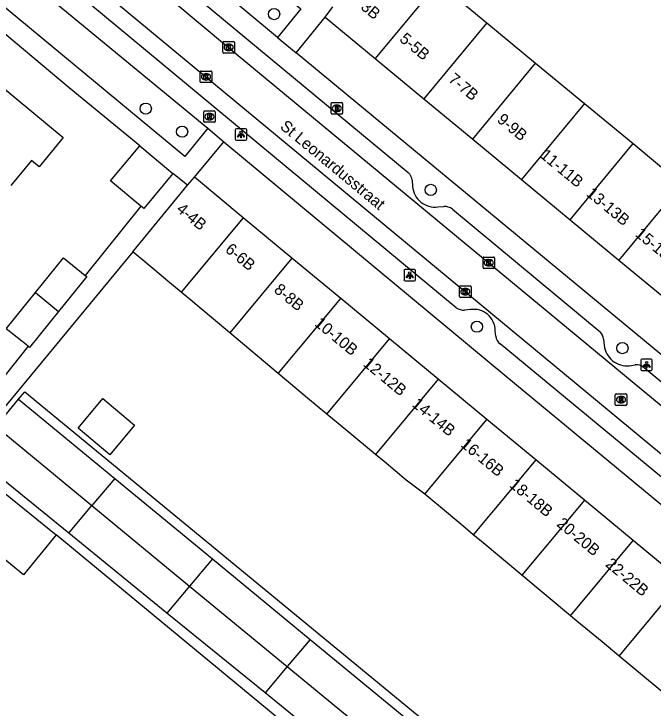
# Model space of a CAD drawing. Extents: x 162074 to 163034, y 381824 to 382557.
# Drawn here: x 162449 to 162504.7, y 382186.3 to 382246.8 of the extents above; entities that cross this region are included whole.
import ezdxf

# ---------------------------------------------------------------- set-up
doc = ezdxf.new("R2010")
doc.units = 0
for name, color, linetype in [('IMGEO_Boom', 7, 'Continuous'), ('IMGEO_Brandkraan', 7, 'Continuous'), ('IMGEO_Kolk', 7, 'Continuous'), ('IMGEO_Lichtpunt', 7, 'Continuous'), ('IMGEO_Muur', 7, 'Continuous'), ('IMGEO_Openbare_ruimte_label', 7, 'Continuous'), ('IMGEO_Pand', 7, 'Continuous'), ('IMGEO_Pand_nummerreeks', 7, 'Continuous'), ('IMGEO_Rijbaan_lokaal_open', 7, 'Continuous'), ('IMGEO_Rioolput', 7, 'Continuous'), ('IMGEO_Voetpad_open', 7, 'Continuous')]:
    doc.layers.add(name, color=color, linetype=linetype)

msp = doc.modelspace()

# ---------------------------------------------------------------- linework, layer by layer
at = {"layer": 'IMGEO_Boom'}
for centre in [(162471.704, 382246.766), (162460.522, 382238.531), (162463.692, 382236.523), (162485.349, 382231.451), (162489.366, 382219.536), (162502.038, 382217.668)]:
    msp.add_circle(centre, 0.489, dxfattribs=at)
at = {"layer": 'IMGEO_Brandkraan'}
for p, q in [((162476.665, 382238.132), (162476.665, 382238.984)), ((162476.74, 382239.058), (162477.592, 382239.058)), ((162477.153, 382238.838), (162477.178, 382238.838)), ((162477.666, 382238.984), (162477.666, 382238.132)), ((162477.176, 382238.278), (162477.151, 382238.278)), ((162477.592, 382238.058), (162476.74, 382238.058))]:
    msp.add_line(p, q, dxfattribs=at)
for points in [[(162476.665, 382238.132), (162476.665, 382238.984)], [(162476.74, 382239.058), (162477.592, 382239.058)], [(162477.013, 382238.758), (162477.013, 382238.358), (162477.226, 382238.358)], [(162477.244, 382238.758), (162477.013, 382238.758)], [(162477.666, 382238.984), (162477.666, 382238.132)], [(162477.192, 382238.677), (162477.138, 382238.677), (162477.138, 382238.601)], [(162477.138, 382238.601), (162477.191, 382238.601)], [(162477.2, 382238.525), (162477.138, 382238.525), (162477.138, 382238.444)], [(162477.138, 382238.444), (162477.2, 382238.444)], [(162477.592, 382238.058), (162476.74, 382238.058)]]:
    msp.add_lwpolyline(points, dxfattribs=at)
for centre, radius, start, end in [((162476.742, 382238.982), 0.0765, 91.55205, 178.44795), ((162476.742, 382238.982), 0.0765, 91.55205, 178.44795), ((162477.248, 382238.613), 0.145, 59.4692, 91.53667), ((162477.273, 382238.66), 0.0922, 285.51372, 58.15012), ((162477.59, 382238.982), 0.0765, 1.55205, 88.44795), ((162477.59, 382238.982), 0.0765, 1.55205, 88.44795), ((162476.742, 382238.134), 0.0765, 181.55205, 268.44795), ((162476.742, 382238.134), 0.0765, 181.55205, 268.44795), ((162477.193, 382238.639), 0.0379, 267.82845, 90.93552), ((162477.201, 382238.484), 0.0404, 269.87594, 90.50774), ((162477.232, 382238.609), 0.251, 268.66757, 293.53466), ((162477.278, 382238.468), 0.105, 301.31148, 78.98903), ((162477.59, 382238.134), 0.0765, 271.55205, 358.44795), ((162477.59, 382238.134), 0.0765, 271.55205, 358.44795)]:
    msp.add_arc(centre, radius, start, end, dxfattribs=at)
for centre, major_axis, ratio, start_param, end_param in [((162477.152, 382238.558), (-0.387, 0.002), 0.722429, 4.712389, 7.853982), ((162477.177, 382238.558), (-0.39, 0.002), 0.717154, 1.570796, 4.712389)]:
    msp.add_ellipse(centre, major_axis=major_axis, ratio=ratio, start_param=start_param, end_param=end_param, dxfattribs=at)
at = {"layer": 'IMGEO_Kolk'}
for p, q in [((162467.242, 382243.437), (162467.242, 382244.289)), ((162467.317, 382244.363), (162468.169, 382244.363)), ((162468.243, 382244.289), (162468.243, 382243.437)), ((162467.753, 382243.583), (162467.728, 382243.583)), ((162467.73, 382244.143), (162467.755, 382244.143)), ((162468.169, 382243.363), (162467.317, 382243.363)), ((162465.273, 382240.876), (162465.273, 382241.728)), ((162465.348, 382241.802), (162466.2, 382241.802)), ((162466.274, 382241.728), (162466.274, 382240.876)), ((162465.761, 382241.582), (162465.786, 382241.582)), ((162466.2, 382240.802), (162465.348, 382240.802)), ((162465.784, 382241.022), (162465.759, 382241.022)), ((162489.896, 382224.679), (162489.896, 382225.531)), ((162489.971, 382225.605), (162490.823, 382225.605)), ((162490.897, 382225.531), (162490.897, 382224.679)), ((162490.407, 382224.825), (162490.382, 382224.825)), ((162490.384, 382225.385), (162490.409, 382225.385)), ((162490.823, 382224.605), (162489.971, 382224.605)), ((162487.856, 382222.165), (162487.856, 382223.017)), ((162487.931, 382223.091), (162488.783, 382223.091)), ((162488.857, 382223.017), (162488.857, 382222.165)), ((162488.344, 382222.871), (162488.369, 382222.871)), ((162488.783, 382222.091), (162487.931, 382222.091)), ((162488.367, 382222.311), (162488.342, 382222.311))]:
    msp.add_line(p, q, dxfattribs=at)
for points in [[(162467.242, 382243.437), (162467.242, 382244.289)], [(162467.317, 382244.363), (162468.169, 382244.363)], [(162468.243, 382244.289), (162468.243, 382243.437)], [(162467.563, 382244.063), (162467.686, 382244.063), (162467.686, 382243.912), (162467.816, 382244.063), (162467.98, 382244.063), (162467.834, 382243.912), (162467.987, 382243.663), (162467.835, 382243.663), (162467.75, 382243.827), (162467.686, 382243.76), (162467.686, 382243.663), (162467.563, 382243.663), (162467.563, 382244.063)], [(162468.169, 382243.363), (162467.317, 382243.363)], [(162465.273, 382240.876), (162465.273, 382241.728)], [(162465.348, 382241.802), (162466.2, 382241.802)], [(162466.274, 382241.728), (162466.274, 382240.876)], [(162465.594, 382241.502), (162465.717, 382241.502), (162465.717, 382241.351), (162465.847, 382241.502), (162466.011, 382241.502), (162465.865, 382241.351), (162466.018, 382241.102), (162465.866, 382241.102), (162465.781, 382241.266), (162465.717, 382241.199), (162465.717, 382241.102), (162465.594, 382241.102), (162465.594, 382241.502)], [(162466.2, 382240.802), (162465.348, 382240.802)], [(162489.896, 382224.679), (162489.896, 382225.531)], [(162489.971, 382225.605), (162490.823, 382225.605)], [(162490.897, 382225.531), (162490.897, 382224.679)], [(162490.217, 382225.305), (162490.34, 382225.305), (162490.34, 382225.154), (162490.47, 382225.305), (162490.634, 382225.305), (162490.488, 382225.154), (162490.641, 382224.905), (162490.489, 382224.905), (162490.404, 382225.069), (162490.34, 382225.002), (162490.34, 382224.905), (162490.217, 382224.905), (162490.217, 382225.305)], [(162490.823, 382224.605), (162489.971, 382224.605)], [(162487.856, 382222.165), (162487.856, 382223.017)], [(162487.931, 382223.091), (162488.783, 382223.091)], [(162488.857, 382223.017), (162488.857, 382222.165)], [(162488.177, 382222.791), (162488.3, 382222.791), (162488.3, 382222.64), (162488.43, 382222.791), (162488.594, 382222.791), (162488.448, 382222.64), (162488.601, 382222.391), (162488.449, 382222.391), (162488.364, 382222.555), (162488.3, 382222.488), (162488.3, 382222.391), (162488.177, 382222.391), (162488.177, 382222.791)], [(162488.783, 382222.091), (162487.931, 382222.091)]]:
    msp.add_lwpolyline(points, dxfattribs=at)
for centre, start, end in [((162467.319, 382244.287), 91.55205, 178.44795), ((162467.319, 382244.287), 91.55205, 178.44795), ((162468.167, 382244.287), 1.55205, 88.44795), ((162468.167, 382244.287), 1.55205, 88.44795), ((162467.319, 382243.439), 181.55205, 268.44795), ((162467.319, 382243.439), 181.55205, 268.44795), ((162468.167, 382243.439), 271.55205, 358.44795), ((162468.167, 382243.439), 271.55205, 358.44795), ((162465.35, 382241.726), 91.55205, 178.44795), ((162465.35, 382241.726), 91.55205, 178.44795), ((162466.198, 382241.726), 1.55205, 88.44795), ((162466.198, 382241.726), 1.55205, 88.44795), ((162465.35, 382240.878), 181.55205, 268.44795), ((162465.35, 382240.878), 181.55205, 268.44795), ((162466.198, 382240.878), 271.55205, 358.44795), ((162466.198, 382240.878), 271.55205, 358.44795), ((162489.973, 382225.529), 91.55205, 178.44795), ((162489.973, 382225.529), 91.55205, 178.44795), ((162490.821, 382225.529), 1.55205, 88.44795), ((162490.821, 382225.529), 1.55205, 88.44795), ((162489.973, 382224.681), 181.55205, 268.44795), ((162489.973, 382224.681), 181.55205, 268.44795), ((162490.821, 382224.681), 271.55205, 358.44795), ((162490.821, 382224.681), 271.55205, 358.44795), ((162487.933, 382223.015), 91.55205, 178.44795), ((162487.933, 382223.015), 91.55205, 178.44795), ((162488.781, 382223.015), 1.55205, 88.44795), ((162488.781, 382223.015), 1.55205, 88.44795), ((162487.933, 382222.167), 181.55205, 268.44795), ((162487.933, 382222.167), 181.55205, 268.44795), ((162488.781, 382222.167), 271.55205, 358.44795), ((162488.781, 382222.167), 271.55205, 358.44795)]:
    msp.add_arc(centre, 0.0765, start, end, dxfattribs=at)
for centre, major_axis, ratio, start_param, end_param in [((162467.729, 382243.863), (-0.387, 0.002), 0.722429, 4.712389, 7.853982), ((162467.754, 382243.863), (-0.39, 0.002), 0.717154, 1.570796, 4.712389), ((162465.76, 382241.302), (-0.387, 0.002), 0.722429, 4.712389, 7.853982), ((162465.785, 382241.302), (-0.39, 0.002), 0.717154, 1.570796, 4.712389), ((162490.383, 382225.105), (-0.387, 0.002), 0.722429, 4.712389, 7.853982), ((162490.408, 382225.105), (-0.39, 0.002), 0.717154, 1.570796, 4.712389), ((162488.343, 382222.591), (-0.387, 0.002), 0.722429, 4.712389, 7.853982), ((162488.368, 382222.591), (-0.39, 0.002), 0.717154, 1.570796, 4.712389)]:
    msp.add_ellipse(centre, major_axis=major_axis, ratio=ratio, start_param=start_param, end_param=end_param, dxfattribs=at)
at = {"layer": 'IMGEO_Lichtpunt'}
for p, q in [((162468.319, 382236.679), (162468.319, 382235.872)), ((162468.319, 382236.679), (162468.319, 382235.872)), ((162469.221, 382236.774), (162468.413, 382236.774)), ((162469.221, 382236.774), (162468.413, 382236.774)), ((162469.315, 382235.872), (162469.315, 382236.679)), ((162469.315, 382235.872), (162469.315, 382236.679)), ((162468.413, 382235.778), (162469.221, 382235.778)), ((162468.413, 382235.778), (162469.221, 382235.778)), ((162483.015, 382224.426), (162483.015, 382223.619)), ((162483.015, 382224.426), (162483.015, 382223.619)), ((162483.917, 382224.521), (162483.109, 382224.521)), ((162483.917, 382224.521), (162483.109, 382224.521)), ((162484.011, 382223.619), (162484.011, 382224.426)), ((162484.011, 382223.619), (162484.011, 382224.426)), ((162483.109, 382223.525), (162483.917, 382223.525)), ((162483.109, 382223.525), (162483.917, 382223.525)), ((162503.644, 382216.622), (162503.644, 382215.815)), ((162503.644, 382216.622), (162503.644, 382215.815)), ((162504.546, 382216.717), (162503.738, 382216.717)), ((162504.546, 382216.717), (162503.738, 382216.717)), ((162504.64, 382215.815), (162504.64, 382216.622)), ((162504.64, 382215.815), (162504.64, 382216.622)), ((162503.738, 382215.721), (162504.546, 382215.721)), ((162503.738, 382215.721), (162504.546, 382215.721))]:
    msp.add_line(p, q, dxfattribs=at)
for points in [[(162468.693, 382236.343), (162468.732, 382236.315), (162468.544, 382236.053), (162468.506, 382236.08), (162468.693, 382236.343)], [(162468.795, 382236.295), (162468.842, 382236.295), (162468.842, 382235.973), (162468.795, 382235.973), (162468.795, 382236.295)], [(162468.905, 382236.315), (162468.943, 382236.342), (162469.13, 382236.08), (162469.091, 382236.052), (162468.905, 382236.315)], [(162483.389, 382224.09), (162483.428, 382224.062), (162483.24, 382223.8), (162483.202, 382223.827), (162483.389, 382224.09)], [(162483.491, 382224.042), (162483.538, 382224.042), (162483.538, 382223.72), (162483.491, 382223.72), (162483.491, 382224.042)], [(162483.601, 382224.062), (162483.639, 382224.089), (162483.826, 382223.827), (162483.787, 382223.799), (162483.601, 382224.062)], [(162504.018, 382216.286), (162504.057, 382216.258), (162503.869, 382215.996), (162503.831, 382216.023), (162504.018, 382216.286)], [(162504.12, 382216.238), (162504.167, 382216.238), (162504.167, 382215.916), (162504.12, 382215.916), (162504.12, 382216.238)], [(162504.23, 382216.258), (162504.268, 382216.285), (162504.455, 382216.023), (162504.416, 382215.995), (162504.23, 382216.258)]]:
    msp.add_lwpolyline(points, dxfattribs=at)
for centre in [(162468.818, 382236.477), (162483.514, 382224.224), (162504.143, 382216.42)]:
    msp.add_circle(centre, 0.0994, dxfattribs=at)
for centre, start, end in [((162468.413, 382236.679), 90, 180), ((162468.413, 382236.679), 90, 180), ((162469.221, 382236.679), 0, 90), ((162469.221, 382236.679), 0, 90), ((162468.413, 382235.872), 180, 270), ((162468.413, 382235.872), 180, 270), ((162469.221, 382235.872), 270, 0), ((162469.221, 382235.872), 270, 360), ((162483.109, 382224.426), 90, 180), ((162483.109, 382224.426), 90, 180), ((162483.917, 382224.426), 0, 90), ((162483.917, 382224.426), 0, 90), ((162483.109, 382223.619), 180, 270), ((162483.109, 382223.619), 180, 270), ((162483.917, 382223.619), 270, 0), ((162483.917, 382223.619), 270, 360), ((162503.738, 382216.622), 90, 180), ((162503.738, 382216.622), 90, 180), ((162504.546, 382216.622), 0, 90), ((162504.546, 382216.622), 0, 90), ((162503.738, 382215.815), 180, 270), ((162503.738, 382215.815), 180, 270), ((162504.546, 382215.815), 270, 0), ((162504.546, 382215.815), 270, 360)]:
    msp.add_arc(centre, 0.0946, start, end, dxfattribs=at)
at = {"layer": 'IMGEO_Muur'}
msp.add_lwpolyline([(162459.998, 382235.296), (162453.858, 382240.334)], dxfattribs=at)
at = {"layer": 'IMGEO_Pand'}
for points in [[(162485.979, 382249.511), (162480.503, 382242.894)], [(162485.979, 382249.511), (162488.441, 382247.475), (162490.227, 382246)], [(162476.155, 382246.489), (162476.81, 382247.387)], [(162476.155, 382246.489), (162480.503, 382242.894)], [(162490.227, 382246), (162484.75, 382239.382)], [(162490.227, 382246), (162494.475, 382242.489)], [(162441.225, 382238.09), (162445.122, 382242.796), (162453.328, 382236.001), (162451.227, 382233.463), (162450.568, 382234.014), (162448.774, 382231.847)], [(162480.503, 382242.894), (162484.75, 382239.382)], [(162488.996, 382235.869), (162494.475, 382242.489)], [(162494.475, 382242.489), (162498.723, 382238.979)], [(162484.75, 382239.382), (162488.996, 382235.869)], [(162498.723, 382238.979), (162493.243, 382232.357)], [(162498.723, 382238.979), (162502.983, 382235.483)], [(162488.996, 382235.869), (162493.243, 382232.357)], [(162460.094, 382230.03), (162457.457, 382232.246), (162459.998, 382235.296)], [(162459.998, 382235.296), (162462.887, 382232.868)], [(162497.49, 382228.845), (162502.983, 382235.483)], [(162502.983, 382235.483), (162507.218, 382231.957)], [(162462.887, 382232.868), (162460.346, 382229.818), (162460.094, 382230.03)], [(162464.155, 382231.869), (162464.763, 382232.548)], [(162469.013, 382229.032), (162464.763, 382232.548)], [(162493.243, 382232.357), (162497.49, 382228.845)], [(162459.396, 382226.044), (162464.155, 382231.869)], [(162507.218, 382231.957), (162501.737, 382225.333)], [(162469.013, 382229.032), (162463.605, 382222.537)], [(162473.259, 382225.518), (162469.013, 382229.032)], [(162497.49, 382228.845), (162501.737, 382225.333)], [(162463.605, 382222.537), (162462.453, 382223.497), (162461.302, 382224.456), (162459.396, 382226.044)], [(162450.909, 382222.51), (162453.344, 382225.536), (162455.245, 382224.005)], [(162473.259, 382225.518), (162467.837, 382219.006)], [(162477.505, 382222.005), (162473.259, 382225.518)], [(162501.737, 382225.333), (162505.984, 382221.82)], [(162455.245, 382224.005), (162455.377, 382223.899), (162452.92, 382220.847)], [(162450.274, 382217.827), (162448.372, 382219.358), (162450.909, 382222.51)], [(162450.909, 382222.51), (162452.92, 382220.847)], [(162467.837, 382219.006), (162466.41, 382220.197), (162464.266, 382221.986), (162463.605, 382222.537)], [(162472.05, 382215.455), (162477.505, 382222.005)], [(162481.751, 382218.492), (162477.505, 382222.005)], [(162452.92, 382220.847), (162450.405, 382217.722), (162450.274, 382217.827)], [(162472.05, 382215.455), (162467.837, 382219.006)], [(162476.283, 382211.925), (162481.751, 382218.492)], [(162485.997, 382214.978), (162481.751, 382218.492)], [(162476.283, 382211.925), (162474.61, 382213.32), (162473.683, 382214.093), (162472.05, 382215.455)], [(162485.997, 382214.978), (162480.527, 382208.41)], [(162490.243, 382211.465), (162485.997, 382214.978)], [(162447.459, 382210.847), (162449.439, 382213.218)], [(162449.439, 382213.218), (162457.82, 382206.316)], [(162457.397, 382208.378), (162454.63, 382210.687), (162456.786, 382213.272), (162459.554, 382210.963), (162457.397, 382208.378)], [(162480.527, 382208.41), (162478.131, 382210.408), (162476.283, 382211.925)], [(162484.818, 382204.95), (162490.243, 382211.465)], [(162494.489, 382207.952), (162490.243, 382211.465)], [(162447.459, 382210.847), (162455.833, 382203.951)], [(162453.812, 382201.546), (162445.403, 382208.384)], [(162484.818, 382204.95), (162483.217, 382206.167), (162481.278, 382207.784), (162480.527, 382208.41)], [(162494.489, 382207.952), (162489.051, 382201.422)], [(162498.734, 382204.438), (162494.489, 382207.952)], [(162457.82, 382206.316), (162455.833, 382203.951)], [(162457.82, 382206.316), (162466.328, 382199.311)], [(162452.706, 382201.422), (162449.875, 382197.935), (162445.311, 382201.641), (162448.142, 382205.128)], [(162448.142, 382205.128), (162452.706, 382201.422)], [(162489.051, 382201.422), (162488.347, 382202.009), (162486.707, 382203.376), (162484.818, 382204.95)], [(162498.734, 382204.438), (162493.276, 382197.884)], [(162502.98, 382200.925), (162498.734, 382204.438)], [(162453.812, 382201.546), (162455.833, 382203.951)], [(162455.833, 382203.951), (162464.341, 382196.946)], [(162462.363, 382194.592), (162453.812, 382201.546)], [(162493.276, 382197.884), (162489.74, 382200.847), (162489.051, 382201.422)], [(162497.509, 382194.355), (162502.98, 382200.925)], [(162507.226, 382197.412), (162502.98, 382200.925)], [(162466.328, 382199.311), (162464.341, 382196.946)], [(162466.328, 382199.311), (162474.834, 382192.306)], [(162497.509, 382194.355), (162493.276, 382197.884)], [(162501.761, 382190.848), (162507.226, 382197.412)], [(162464.341, 382196.946), (162462.363, 382194.592)], [(162464.341, 382196.946), (162472.847, 382189.941)], [(162470.913, 382187.639), (162462.363, 382194.592)], [(162501.761, 382190.848), (162500.267, 382192.084), (162498.054, 382193.9), (162497.509, 382194.355)], [(162474.834, 382192.306), (162472.847, 382189.941)], [(162474.834, 382192.306), (162483.342, 382185.3)], [(162506.005, 382187.333), (162501.761, 382190.848)], [(162472.847, 382189.941), (162470.913, 382187.639)], [(162472.847, 382189.941), (162481.355, 382182.935)], [(162479.465, 382180.685), (162470.913, 382187.639)]]:
    msp.add_lwpolyline(points, dxfattribs=at)
at = {"layer": 'IMGEO_Rijbaan_lokaal_open'}
for points in [[(162455.575, 382254.047), (162467.743, 382243.863), (162583.48, 382148.075)], [(162576.743, 382149.513), (162505.451, 382208.42), (162453.427, 382251.529)]]:
    msp.add_lwpolyline(points, dxfattribs=at)
at = {"layer": 'IMGEO_Rioolput'}
for p, q in [((162465.574, 382237.411), (162465.574, 382238.263)), ((162465.649, 382238.337), (162466.501, 382238.337)), ((162466.062, 382238.117), (162466.087, 382238.117)), ((162466.575, 382238.263), (162466.575, 382237.411)), ((162466.085, 382237.557), (162466.06, 382237.557)), ((162466.501, 382237.337), (162465.649, 382237.337)), ((162501.418, 382212.761), (162501.418, 382213.613)), ((162501.493, 382213.687), (162502.345, 382213.687)), ((162501.906, 382213.467), (162501.931, 382213.467)), ((162502.419, 382213.613), (162502.419, 382212.761)), ((162501.929, 382212.907), (162501.904, 382212.907)), ((162502.345, 382212.687), (162501.493, 382212.687))]:
    msp.add_line(p, q, dxfattribs=at)
for points in [[(162465.574, 382237.411), (162465.574, 382238.263)], [(162465.649, 382238.337), (162466.501, 382238.337)], [(162466.575, 382238.263), (162466.575, 382237.411)], [(162466.163, 382238.035), (162465.911, 382238.037), (162465.911, 382237.637)], [(162465.911, 382237.637), (162466.035, 382237.637), (162466.035, 382237.799), (162466.046, 382237.799)], [(162466.089, 382237.956), (162466.035, 382237.956), (162466.035, 382237.875)], [(162466.035, 382237.875), (162466.087, 382237.875)], [(162466.093, 382237.77), (162466.164, 382237.637), (162466.304, 382237.637), (162466.239, 382237.763)], [(162466.501, 382237.337), (162465.649, 382237.337)], [(162501.418, 382212.761), (162501.418, 382213.613)], [(162501.493, 382213.687), (162502.345, 382213.687)], [(162502.007, 382213.385), (162501.755, 382213.387), (162501.755, 382212.987)], [(162502.419, 382213.613), (162502.419, 382212.761)], [(162501.755, 382212.987), (162501.879, 382212.987), (162501.879, 382213.149), (162501.89, 382213.149)], [(162501.933, 382213.306), (162501.879, 382213.306), (162501.879, 382213.225)], [(162501.879, 382213.225), (162501.931, 382213.225)], [(162501.937, 382213.12), (162502.008, 382212.987), (162502.148, 382212.987), (162502.083, 382213.113)], [(162502.345, 382212.687), (162501.493, 382212.687)]]:
    msp.add_lwpolyline(points, dxfattribs=at)
for centre, radius, start, end in [((162465.651, 382238.261), 0.0765, 91.55205, 178.44795), ((162465.651, 382238.261), 0.0765, 91.55205, 178.44795), ((162466.499, 382238.261), 0.0765, 1.55205, 88.44795), ((162466.499, 382238.261), 0.0765, 1.55205, 88.44795), ((162466.045, 382237.746), 0.0533, 26.02933, 88.69889), ((162466.071, 382238.064), 0.19, 274.7715, 282.96867), ((162466.095, 382237.86), 0.0964, 77.00612, 93.18647), ((162466.109, 382237.917), 0.0378, 276.66336, 79.67722), ((162466.162, 382237.925), 0.109, 350.36119, 89.41601), ((162466.16, 382237.925), 0.112, 277.58423, 350.98172), ((162466.144, 382237.71), 0.108, 29.51342, 73.79051), ((162465.651, 382237.413), 0.0765, 181.55205, 268.44795), ((162465.651, 382237.413), 0.0765, 181.55205, 268.44795), ((162466.499, 382237.413), 0.0765, 271.55205, 358.44795), ((162466.499, 382237.413), 0.0765, 271.55205, 358.44795), ((162501.495, 382213.611), 0.0765, 91.55205, 178.44795), ((162501.495, 382213.611), 0.0765, 91.55205, 178.44795), ((162502.006, 382213.275), 0.109, 350.36119, 89.41601), ((162502.343, 382213.611), 0.0765, 1.55205, 88.44795), ((162502.343, 382213.611), 0.0765, 1.55205, 88.44795), ((162501.495, 382212.763), 0.0765, 181.55205, 268.44795), ((162501.495, 382212.763), 0.0765, 181.55205, 268.44795), ((162501.889, 382213.096), 0.0533, 26.02933, 88.69889), ((162501.915, 382213.414), 0.19, 274.7715, 282.96867), ((162501.939, 382213.21), 0.0964, 77.00612, 93.18647), ((162501.953, 382213.267), 0.0378, 276.66336, 79.67722), ((162502.004, 382213.275), 0.112, 277.58423, 350.98172), ((162501.988, 382213.06), 0.108, 29.51342, 73.79051), ((162502.343, 382212.763), 0.0765, 271.55205, 358.44795), ((162502.343, 382212.763), 0.0765, 271.55205, 358.44795)]:
    msp.add_arc(centre, radius, start, end, dxfattribs=at)
for centre, major_axis, ratio, start_param, end_param in [((162466.061, 382237.837), (-0.387, 0.002), 0.722429, 4.712389, 7.853982), ((162466.086, 382237.837), (-0.39, 0.002), 0.717154, 1.570796, 4.712389), ((162501.905, 382213.187), (-0.387, 0.002), 0.722429, 4.712389, 7.853982), ((162501.93, 382213.187), (-0.39, 0.002), 0.717154, 1.570796, 4.712389)]:
    msp.add_ellipse(centre, major_axis=major_axis, ratio=ratio, start_param=start_param, end_param=end_param, dxfattribs=at)
at = {"layer": 'IMGEO_Voetpad_open'}
for points in [[(162457.906, 382260.427), (162474.021, 382247.229), (162471.998, 382244.738)], [(162471.998, 382244.738), (162455.97, 382258.081)], [(162458.327, 382253.762), (162483.379, 382232.961)], [(162449.526, 382250.362), (162465.927, 382236.819)], [(162487.569, 382221.19), (162454.369, 382248.742)], [(162465.927, 382236.819), (162463.917, 382234.37), (162447.507, 382247.934)], [(162473.626, 382243.391), (162476.155, 382246.489)], [(162459.998, 382235.296), (162453.858, 382240.334), (162447.496, 382245.651)], [(162471.998, 382244.738), (162473.626, 382243.391)], [(162528.918, 382197.653), (162473.626, 382243.391)], [(162465.927, 382236.819), (162467.32, 382235.647)], [(162464.763, 382232.548), (162467.32, 382235.647)], [(162467.32, 382235.647), (162491.963, 382215.169), (162522.479, 382189.936)], [(162464.155, 382231.869), (162462.887, 382232.868)], [(162483.727, 382232.286), (162483.766, 382231.751)], [(162460.094, 382230.03), (162455.245, 382224.005)], [(162485.962, 382229.967), (162486.482, 382230.007)], [(162487.228, 382229.772), (162500.09, 382219.102)], [(162459.396, 382226.044), (162434.47, 382195.892)], [(162488.81, 382221.03), (162488.295, 382220.986)], [(162491.015, 382218.703), (162490.956, 382219.177)], [(162500.395, 382218.439), (162500.457, 382217.914)], [(162450.274, 382217.827), (162447.701, 382214.63)], [(162531.722, 382184.707), (162491.402, 382218.04)], [(162502.656, 382216.142), (162503.153, 382216.204)], [(162503.92, 382215.987), (162516.926, 382205.188)], [(162449.439, 382213.218), (162449.979, 382213.874), (162504.869, 382168.675), (162514.495, 382180.304)], [(162485.329, 382153.165), (162495.889, 382165.728), (162452.706, 382201.422)]]:
    msp.add_lwpolyline(points, dxfattribs=at)
for centre, radius, start, end in [((162482.762, 382232.216), 0.968, 4.1742, 50.37304), ((162485.721, 382231.913), 1.961, 184.74831, 277.07183), ((162486.536, 382228.877), 1.131, 52.29303, 92.73672), ((162488.212, 382222.085), 1.102, 234.30581, 274.30434), ((162489.085, 382219.179), 1.871, 359.94263, 98.43833), ((162499.33, 382218.351), 1.069, 4.74029, 44.66742), ((162491.942, 382218.8), 0.932, 185.96347, 234.58164), ((162502.417, 382218.096), 1.968, 185.29744, 276.97738), ((162503.325, 382215.348), 0.874, 47.0569, 101.34852)]:
    msp.add_arc(centre, radius, start, end, dxfattribs=at)

# ---------------------------------------------------------------- texts
at = {"layer": 'IMGEO_Openbare_ruimte_label'}
msp.add_text('St Leonardusstraat', height=1, rotation=320.35582, dxfattribs=at).set_placement((162472.147, 382236.856))
at = {"layer": 'IMGEO_Pand_nummerreeks'}
for s, rotation, p in [('3-3B', 320.40862, (162478.259, 382248.02)), ('5-5B', 320.40862, (162482.556, 382244.466)), ('7-7B', 320.40862, (162486.803, 382240.954)), ('9-9B', 320.40862, (162491.05, 382237.441)), ('11-11B', 320.40862, (162494.798, 382234.341)), ('13-13B', 320.40862, (162498.834, 382231.003)), ('4-4B', 320.39143, (162463.121, 382229.65)), ('15-15B', 320.40862, (162503.08, 382227.491)), ('6-6B', 320.39143, (162467.369, 382226.135)), ('8-8B', 320.39143, (162471.615, 382222.622)), ('10-10B', 320.39143, (162475.151, 382219.695)), ('12-12B', 320.39143, (162479.397, 382216.182)), ('14-14B', 320.39143, (162483.643, 382212.668)), ('16-16B', 320.39143, (162487.889, 382209.155)), ('18-18B', 320.39143, (162492.135, 382205.642)), ('20-20B', 320.39387, (162496.24, 382202.245)), ('22-22B', 320.39143, (162500.486, 382198.731))]:
    msp.add_text(s, height=1, rotation=rotation, dxfattribs=at).set_placement(p)

doc.saveas('drawing.dxf')
